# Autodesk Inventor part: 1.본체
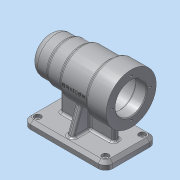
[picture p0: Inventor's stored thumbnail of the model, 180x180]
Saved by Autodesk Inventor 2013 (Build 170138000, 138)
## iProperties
Created: 2016-06
Part Number: 1.본체
Material: 알루미늄 6061
Document SubType Name: Modeling
Designer: dgall
Density: 2.71 g/cm^3
Mass: 673.897 g
Surface Area: 647.222 cm^2
Volume: 248.67 cm^3
Author: dgall
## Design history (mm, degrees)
sketch "스케치1"
  geometry: C1 r 34 at (0, 0); 1 further point
  constraints: 1 centre point, 1 coincident
  dimensions: "d0" = 68 diameter of C1
extrude "돌출1" new body sketch "스케치1" distance "d5" = 28; taper "d6" = 0 deg
sketch "스케치2"
  geometry: C1 r 34 at (0, 0) reference; C2 r 30 at (0, 0)
  constraints: 1 centre point, 1 coincident
  dimensions: "d7" = 60 diameter of C2
extrude "돌출2" join sketch "스케치2" distance "d10" = 39; taper "d11" = 0 deg
sketch "스케치3"
  geometry: C1 r 30 at (0, 0) reference; C2 r 27 at (0, 0)
  constraints: 1 centre point, 1 coincident
  dimensions: "d12" = 54 diameter of C2
extrude "돌출3" join sketch "스케치3" distance "d14" = 20; taper "d15" = 0 deg
sketch "스케치4"
  geometry: C1 r 27 at (0, 0) reference; C2 r 25 at (0, 0)
  constraints: 1 centre point, 1 coincident
  dimensions: "d16" = 50 diameter of C2
extrude "돌출4" join sketch "스케치4" distance "d18" = 25; taper "d19" = 0 deg
sketch "스케치5"
  geometry: L1 (112, 0)-(0, 0); L2 (112, -25)-(112, 25) reference; L3 (106, 0)-(106, 10.5); L4 (106, 10.5)-(103, 10.5); L5 (103, 10.5)-(103, 16); L6 (103, 16)-(99, 16); L7 (99, 16)-(99, 17.5); L8 (99, 17.5)-(81, 17.5); L9 (81, 17.5)-(81, 21); L10 (81, 21)-(69, 21); L11 (69, 21)-(69, 24); L12 (69, 24)-(15, 24); L13 (15, 24)-(15, 21); L14 (15, 21)-(0, 21); L15 (0, 21)-(0, 0)
  constraints: 28 end point, 11 parallel, 2 perpendicular, 1 horizontal, 1 midpoint, 1 point on line
  dimensions: "d20" = 21 diameter of L4 L1; "d22" = 32 diameter of L6 L1; "d23" = 35 diameter of L8 L1; "d24" = 42 diameter of L10 L1; "d25" = 48 diameter of L12 L1; "d26" = 42 diameter of L14 L1; "d27" = 15 distance of L13.end L14.end; "d28" = 54 distance of L11.end L12.end; "d29" = 12 distance of L9.end L10.end; "d30" = 18 distance of L7.end L8.end; "d31" = 4 distance of L5.end L6.end; "d32" = 3 distance of L3.end L4.end
revolve "회전1" sketch "스케치5" stored, may be unused: angle "d33" = 90 deg
fillet "모깎기1" dims "d34" = 10
fillet "모깎기2" dims "d35" = 3
fillet "모깎기3" dims "d36" = 3
fillet "모깎기4" dims "d37" = 0.3
chamfer "모따기1" distance "d38" = 1; stored, may be unused: second distance "d39" = 2, angle "d40" = 45 deg
sketch "스케치6"
  geometry: L1 (-112, -60)-(0, -60); L2 (0, -60)-(0, -70); L3 (0, -70)-(-112, -70); L4 (-112, -70)-(-112, -60); 1 further point
  constraints: 8 end point, 2 parallel, 1 horizontal, 1 perpendicular, 1 point on line
  dimensions: "d41" = 112 distance of L2.end L3.end; "d43" = 10 distance of L1.end L2.end; "d44" = 70 distance from line of L3 point (0, 0)
extrude "돌출5" join sketch "스케치6" stored distance "d45" = 70; taper "d46" = 0 deg
fillet "모깎기5" dims "d47" = 10
chamfer "모따기2" distance "d48" = 4; stored, may be unused: second distance "d49" = 2, angle "d50" = 45 deg
hole "구멍1" diameter "d53" = 5; stored, may be unused: countersink angle "d57" = 90 deg, drill point angle "d59" = 118 deg; dims "d51" = 10, "d52" = 10, "d54" = 6, "d55" = 9, "d56" = 4, "d58" = 8
node "작업 평면1"
sketch "스케치7"
  geometry: L1 (82, -35)-(10, -35); L2 (10, -35)-(10, -27); L3 (10, -27)-(82, -27); L4 (82, -27)-(82, -35); L5 (102, -56)-(102, -6) reference; L6 (-10, -6)-(-10, -56) reference; 2 further points
  constraints: 8 end point, 2 parallel, 1 horizontal, 1 horizontal alignment, 1 midpoint, 1 perpendicular
  dimensions: "d61" = 20 distance between parallel lines of L4 L5; "d62" = 20 distance from line of L6 point (10, -31); "d63" = 8 distance of L3.end L1.start
extrude "돌출6" join sketch "스케치7" stored distance "d64" = 70; taper "d65" = 0 deg
sketch "스케치8"
  geometry: L1 (10, -27)-(82, -27) reference; L2 (42, -3)-(50, -3); L3 (50, -3)-(50, -59); L4 (50, -59)-(42, -59); L5 (42, -59)-(42, -3); L6 (92, 4)-(0, 4) reference; L7 (0, -66)-(92, -66) reference; 3 further points
  constraints: 8 end point, 2 midpoint, 2 parallel, 1 horizontal, 1 perpendicular, 1 vertical alignment
  dimensions: "d66" = 8 distance of L2.start L2.end; "d68" = 7 distance between parallel lines of L6 L2; "d69" = 7 distance between parallel lines of L7 L4
extrude "돌출7" join sketch "스케치8" stored distance "d70" = 70; taper "d71" = 0 deg
feature "면 기울기1" dims angle "d72" = 20 deg
feature "면 기울기2" dims angle "d73" = 20 deg
fillet "모깎기6" dims "d74" = 3
fillet "모깎기7" dims "d75" = 3
sketch "스케치9"
  geometry: C1 r 34 at (0, 0) reference; 1 further point
  constraints: 1 horizontal alignment
  dimensions: "d76" = 26 distance of C1.centre point (26, 0)
hole "구멍2" sketch "스케치9" at (26, 0) diameter "d77" = 3.242; stored, may be unused: countersink angle "d81" = 90 deg, drill point angle "d83" = 118 deg; dims "d78" = 8, "d79" = 9, "d80" = 4, "d82" = 11
node "작업 평면2"
sketch "스케치10"
  geometry: L1 (28, -34)-(28, 34) reference; 3 further points
  constraints: 1 horizontal alignment, 1 midpoint, 1 other
  dimensions: "d87" = 48 distance from line of L1 point (-20, 0)
feature "엠보싱1" sketch "스케치10" dims "d88" = 0.5, "d89" = 0
node "솔리드1"
mirror "대칭1"
mirror "대칭2"
pattern_circular "원형 패턴1" dims angle "d85" = 360 deg
